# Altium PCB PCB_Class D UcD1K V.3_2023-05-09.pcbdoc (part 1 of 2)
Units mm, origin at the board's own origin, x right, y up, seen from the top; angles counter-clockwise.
Board outline 217.55 x 90.42 mm, 2 copper layers (Top Layer, Bottom Layer); 170 components, 120 nets, 574 pads, 13 vias.
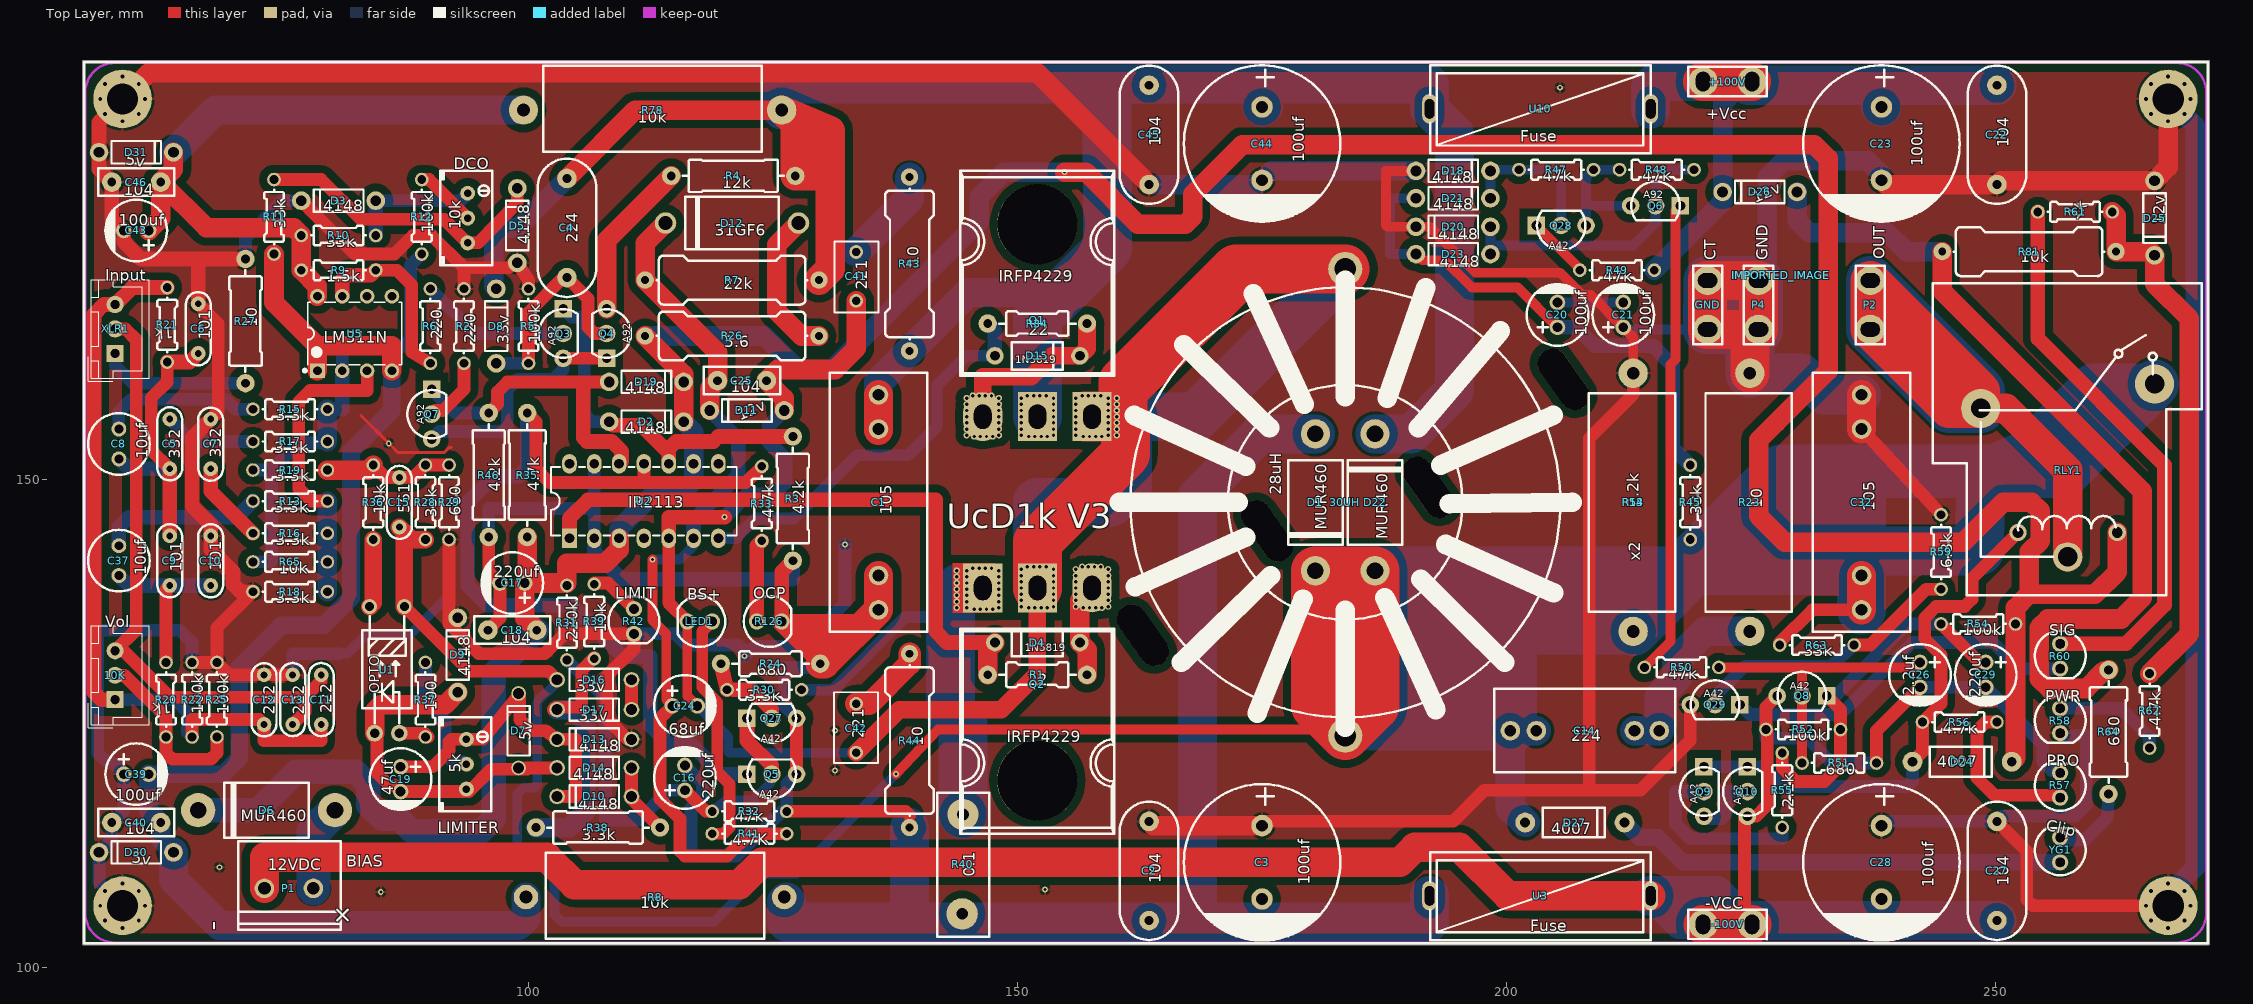
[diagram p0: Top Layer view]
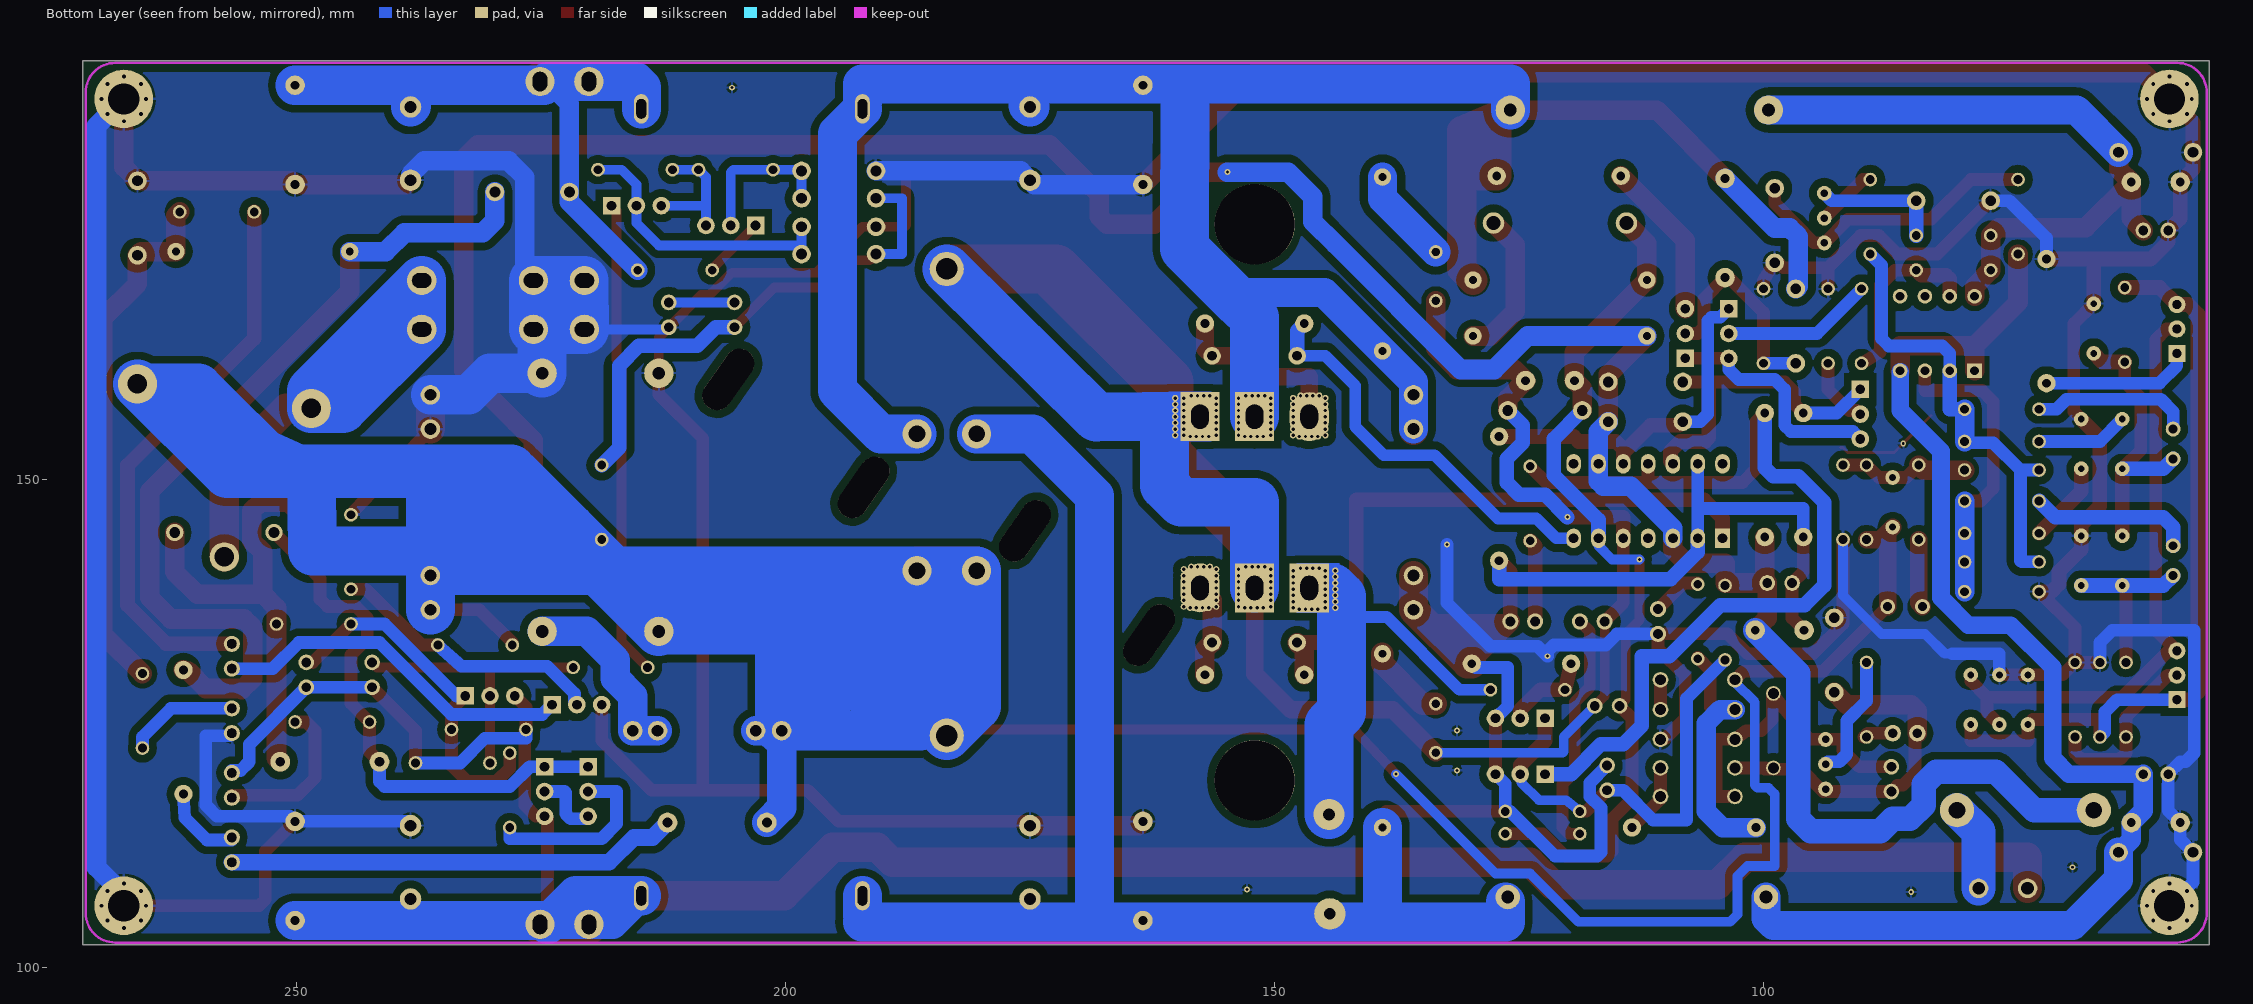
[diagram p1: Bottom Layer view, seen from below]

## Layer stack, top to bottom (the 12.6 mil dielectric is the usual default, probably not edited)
Top Solder: solder mask 0.0102, Solder Resist, Dk 3.5
Top Layer: signal copper 0.0356
Dielectric1: dielectric 0.32, FR-4, Dk 4.8
Bottom Layer: signal copper 0.0356
Bottom Solder: solder mask 0.0102, Solder Resist, Dk 3.5

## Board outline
54.356,192.786 271.907,192.786 271.907,102.362 54.356,102.362

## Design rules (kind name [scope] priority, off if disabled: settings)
Clearance [All] p1: gap=0.8 ignorepadtopadclearanceinfootprint=FALSE
PolygonConnect [All] p1: connectstyle=Relief reliefconductorwidth=0.254 reliefentries=4 polygonreliefangle="90 Angle" airgapwidth=0.254
RoutingVias [All] p1: holewidth=0.711 width=1.27 viastyle="Through Hole" minholewidth=0.711 minwidth=1.27 maxholewidth=0.711 maxwidth=1.27
SolderMaskExpansion [All] p1: expansion=0.102
Width [All] p1: maxlimit=0.254 minlimit=0.254 preferedwidth=0.254
30 further rules are at their usual default settings.

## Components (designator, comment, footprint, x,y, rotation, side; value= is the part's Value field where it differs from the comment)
10K "Vol" "JST 3P" 57.658,127.425 r90 top
30UH "28uH" "TOROID CORE" 183.515,147.618 r0 top
+100V "+Vcc" "FASTON TAB" 222.631,190.671 r180 top
-100V "-VCC" "FASTON TAB" 222.631,104.438 r180 top
C1 "105" "CAP MYLAR 22MM" 135.763,147.618 r0 top
C2 "104" "MYLAR CAP 10MM" 163.449,109.899 r0 top
C3 "100uf" CAP-TH_BD16.0-P7.50-D1.2-FD 175.006,110.788 r270 top
C4 "224" "MYLAR CAP 10MM" 103.886,175.685 r0 top
C5 "332" CERCAP 63.246,153.587 r180 top
C6 "101" CERCAP 66.167,165.398 r0 top
C7 "332" CERCAP 67.437,153.587 r0 top
C8 "10uf" "NONPOLAR CAP 22UF" 58.039,153.587 r270 top
C9 "101" CERCAP 63.246,141.649 r0 top
C10 "101" CERCAP 67.437,141.649 r0 top
C11 "222" CERCAP 78.74,127.425 r180 top
C12 "222" CERCAP 72.898,127.425 r0 top
C13 "222" CERCAP 75.819,127.425 r180 top
C14 "224" CAP-CBB-18.5*8.5 208.026,124.25 r180 top
C15 "561" CERCAP 86.741,147.618 r0 top
C16 "220uf" CAP-TH_BD6.3-P2.50-D1.0-FD 115.951,119.424 r90 top
C17 "220uf" CAP-TH_BD6.3-P2.50-D1.0-FD 98.298,139.363 r180 top
C18 "104" POLYCAP104 98.298,134.537 r90 top
C19 "47uf" CAP-TH_BD6.3-P2.50-D1.0-FD 86.868,119.297 r270 top
C20 "100uf" CAP-TH_BD6.3-P2.50-D1.0-FD 205.232,166.795 r90 top
C21 "100uf" CAP-TH_BD6.3-P2.50-D1.0-FD 211.963,166.795 r90 top
C22 "104" "MYLAR CAP 10MM" 250.19,185.21 r0 top
C23 "100uf" CAP-TH_BD16.0-P7.50-D1.2-FD 238.379,184.321 r270 top
C24 "68uf" CAP-TH_BD6.3-P2.50-D1.0-FD 115.951,126.79 r0 top
C25 "104" POLYCAP104 121.793,160.064 r270 top
C26 "2.2uf" CAP-TH_BD6.3-P2.50-D1.0-FD 242.316,129.965 r270 top
C27 "104" "MYLAR CAP 10MM" 250.19,109.899 r0 top
C28 "100uf" CAP-TH_BD16.0-P7.50-D1.2-FD 238.379,110.788 r270 top
C29 "220uf" CAP-TH_BD6.3-P2.50-D1.0-FD 249.047,129.965 r270 top
C32 "105" "CAP MYLAR 22MM" 236.347,147.618 r180 top
C37 "10uf" "NONPOLAR CAP 22UF" 58.039,141.649 r270 top
C39 "100uf" CAP-TH_BD6.3-P2.50-D1.0-FD 59.817,119.805 r0 top
C40 "104" POLYCAP104 59.817,114.852 r90 top
C41 "221" "WIMA RED" 133.477,170.732 r270 top
C42 "221" "WIMA RED" 133.477,124.504 r90 top
C43 "100uf" CAP-TH_BD6.3-P2.50-D1.0-FD 59.817,175.431 r180 top
C44 "100uf" CAP-TH_BD16.0-P7.50-D1.2-FD 175.006,184.321 r270 top
C45 "104" "MYLAR CAP 10MM" 163.449,185.21 r0 top
C46 "104" POLYCAP104 59.817,180.384 r90 top
D1 "MUR460" MUR460R#1 180.467,147.618 r270 top
D2 "4148" DO-35R#1 112.014,155.873 r180 top
D3 "4148" DO-35R#1 80.518,178.479 r0 top
D4 "1N5819" DO-41_BD2.4-L4.7-P8.70-D0.9-FD 152.019,133.267 r180 top
D5 "4148" DO-35R#1 98.806,175.939 r270 top
D6 "MUR460" MUR460R#2 73.152,116.122 r180 top
D7 "5v" DO-35R#2 98.933,124.25 r270 top
D8 "33v" DO-35R#1 96.647,165.652 r270 top
D9 "4148" DO-35R#1 92.71,131.997 r270 top
D10 "4148" DO-35R#3 106.68,117.519 r0 top
D11 "12v" DO-35R#1 122.301,157.016 r0 top
D12 "31GF6" DO-201_BD5.3-L9.5-P13.50-D1.4-FD 120.777,176.193 r180 top
D13 "4148" DO-35R#3 106.68,123.361 r0 top
D14 "4148" DO-35R#3 106.68,120.44 r180 top
D15 "1N5819" DO-41_BD2.4-L4.7-P8.70-D0.9-FD 152.019,162.604 r0 top
D16 "33v" DO-35R#3 106.68,129.457 r180 top
D17 "33v" DO-35R#3 106.68,126.409 r180 top
D18 "4148" DO-35R#1 194.564,181.527 r180 top
D19 "4148" DO-35R#1 112.014,159.937 r180 top
D20 "4148" DO-35R#1 194.564,175.812 r0 top
D21 "4148" DO-35R#1 194.564,178.733 r180 top
D22 "MUR460" MUR460R#1 186.563,147.618 r90 top
D23 "4148" DO-35R#1 194.564,173.018 r0 top
D24 "4007" 1N4007R 246.634,121.075 r90 top
D25 "12v" DO-35R#1 266.319,176.701 r90 top
D26 "12v" DO-35R#1 225.933,179.368 r0 top
D27 "4007" 1N4007R 207.01,114.852 r90 top
D30 "5v" DO-35R#1 59.817,111.804 r0 top
D31 "5v" DO-35R#1 59.817,183.432 r180 top
DCO "10k" RES-ADJ-TH_3296W 93.726,176.701 r0 top
GND "CT" "FASTON TAB" 220.599,167.811 r270 top
IMPORTED_IMAGE "Comment" IMPORTED_IMAGE 228.052,170.872 r0 top
IMPORTED_IMAGE "Comment" IMPORTED_IMAGE 228.053,170.872 r0 top
LED1 "BS+" "LED B 5MM" 117.475,135.426 r90 top
LIMITER "5k" RES-ADJ-TH_3296W 93.599,120.821 r0 top
P1 "12VDC" CONN-TH_2P-P5.00_WJ300V-5.00-2P 75.438,108.121 r180 top
P2 "OUT" "FASTON TAB" 237.236,167.811 r90 top
P4 "GND" "FASTON TAB" 225.806,167.811 r270 top
Q1 "IRFP4229" TO-247L 152.019,169.208 r0 top
Q2 "IRFP4229" TO-247L 152.019,126.028 r180 top
Q3 "A92" TO-92-3_L4.8-W3.7-P2.54-R 103.505,164.89 r90 top
Q4 "A92" TO-92-3_L4.8-W3.7-P2.54-R 107.95,164.89 r270 top
Q5 "A42" TO-92-3_L4.8-W3.7-P2.54-R 124.841,119.805 r180 top
Q6 "A92" TO-92-3_L4.8-W3.7-P2.54-R 215.265,177.971 r0 top
Q7 "A92" TO-92-3_L4.8-W3.7-P2.54-R 90.043,156.635 r90 top
Q8 "A42" TO-92-3_L4.8-W3.7-P2.54-R 230.251,127.806 r0 top
Q9 "A42" TO-92-3_L4.8-W3.7-P2.54-R 220.218,118.027 r90 top
Q10 "A42" TO-92-3_L4.8-W3.7-P2.54-R 224.663,118.027 r90 top
Q27 "A42" TO-92-3_L4.8-W3.7-P2.54-R 124.841,125.52 r180 top
Q28 "A42" TO-92-3_L4.8-W3.7-P2.54-R 205.613,175.939 r180 top
Q29 "A42" TO-92-3_L4.8-W3.7-P2.54-R 221.361,126.917 r0 top
R1 "22" AXIAL-0.4R 152.019,129.965 r0 top
R2 "220" AXIAL-0.3R 93.345,165.652 r90 top
R3 "4.2k" "AXIAL-0.5 R" 127,147.872 r270 top
R4 "12k" "AXIAL-0.5 R" 120.777,181.019 r180 top
R5 "100k" AXIAL-0.3R 99.949,165.652 r90 top
R6 "220" AXIAL-0.3R 89.916,165.652 r90 top
R7 "22k" AXIAL-0.7 120.777,170.351 r0 top
R8 "10k" "5WATTS RESISTOR"#1 112.903,107.232 r180 top
R9 "1.5k" AXIAL-0.3R 80.518,171.367 r0 top
R10 "33k" AXIAL-0.3R 80.518,174.923 r0 top
R11 "33k" AXIAL-0.3R 73.914,176.828 r90 top
R12 "100k" AXIAL-0.3R 89.027,176.828 r90 top
R13 "3.3k" AXIAL-0.3R 75.565,147.745 r0 top
R14 "2.2k" "5WATTS RESISTOR"#2 212.979,147.618 r270 top
R15 "3.3k" AXIAL-0.3R 75.565,157.143 r0 top
R16 "3.3k" AXIAL-0.3R 75.565,144.443 r0 top
R17 "3.3k" AXIAL-0.3R 75.565,153.841 r0 top
R18 "3.3k" AXIAL-0.3R 75.565,138.474 r0 top
R19 "3.3k" AXIAL-0.3R 75.565,150.92 r180 top
R20 "1k" AXIAL-0.3R 62.865,127.425 r90 top
R21 "1k" AXIAL-0.3R 62.992,165.779 r270 top
R22 "100k" AXIAL-0.3R 65.532,127.425 r270 top
R23 "10" "5WATTS RESISTOR"#2 224.917,147.618 r270 top
R24 "680" AXIAL-0.4R 124.714,131.108 r180 top
R25 "100k" AXIAL-0.3R 68.072,127.425 r90 top
R26 "5.6" AXIAL-0.7 120.777,164.636 r180 top
R27 "10" "AXIAL-0.5 R" 70.993,166.287 r90 top
R28 "33k" AXIAL-0.3R 89.408,147.618 r270 top
R29 "680" AXIAL-0.3R 91.821,147.618 r90 top
R30 "3.3k" AXIAL-0.3R 124.079,128.441 r180 top
R31 "220k" AXIAL-0.3R 103.886,135.299 r90 top
R32 "47k" AXIAL-0.3R 122.555,115.995 r180 top
R33 "4.7k" AXIAL-0.3R 123.825,147.491 r90 top
R34 "22" AXIAL-0.4R 152.019,165.906 r0 top
R35 "4.7k" "AXIAL-0.5 R" 99.822,150.285 r270 top
R36 "10k" AXIAL-0.3R 84.074,147.618 r90 top
R37 "100" AXIAL-0.3R 89.408,127.425 r270 top
R38 "3.3k" "AXIAL-0.5 R" 106.934,114.344 r180 top
R39 "10k" AXIAL-0.3R 106.68,135.426 r270 top
R40 "0.1" "BPR56  5W" 144.399,110.723 r0 top
R41 "4.7K" AXIAL-0.3R 122.555,113.709 r0 top
R42 "LIMIT" "LED R 5MM" 110.744,135.426 r180 top
R43 "10" AXIAL-0.7 138.938,172.002 r90 top
R44 "10" AXIAL-0.7 138.938,123.234 r270 top
R45 "33k" AXIAL-0.3R 218.821,147.618 r270 top
R46 "4.2k" "AXIAL-0.5 R" 95.885,150.285 r270 top
R47 "47k" AXIAL-0.3R 205.105,181.654 r0 top
R48 "47k" AXIAL-0.3R 215.392,181.654 r0 top
R49 "47k" AXIAL-0.3R 211.328,171.367 r180 top
R50 "47k" AXIAL-0.3R 217.932,130.727 r0 top
R51 "680" AXIAL-0.3R 234.061,120.948 r0 top
R52 "100k" AXIAL-0.3R 230.378,124.377 r180 top
R53 "x2" "5WATTS RESISTOR"#2 212.979,147.618 r270 top
R54 "100k" AXIAL-0.3R 248.285,135.172 r180 top
R55 "2.2k" AXIAL-0.3R 228.219,118.154 r270 top
R56 "4.7k" AXIAL-0.3R 246.38,125.139 r0 top
R57 "PRO" "LED R 5MM" 256.667,118.662 r0 top
R58 "PWR" "LED B 5MM" 256.667,125.266 r180 top
R59 "6.8k" AXIAL-0.3R 244.475,142.538 r270 top
R60 "SIG" "LED G 5MM" 256.667,131.87 r180 top
R61 "1k" AXIAL-0.3R 258.191,177.336 r180 top
R62 "4.7k" AXIAL-0.3R 265.811,126.282 r270 top
R63 "33k" AXIAL-0.3R 231.775,133.013 r180 top
R64 "680" "AXIAL-0.5 R" 261.62,123.996 r270 top
R65 "10k" AXIAL-0.3R 75.565,141.522 r0 top
R78 "10k" "5WATTS RESISTOR"#2 112.649,187.75 r180 top
R81 "10k" AXIAL-0.7 253.492,173.272 r0 top
R126 "OCP" "LED R 5MM" 124.587,135.426 r270 top
RLY1 "Relay" "SLA RELAY 12V" 257.429,153.968 r90 top
U1 "OPTO" OPTO 85.471,130.6 r270 top
U2 "IR2113" DIP-14_L19.0-W7.0-P2.54-LS7.6-BL 111.76,147.745 r0 top
U3 "Fuse" FUSE-TH_L22.6-W9.0 203.454,107.359 r180 top
U5 "LM311N" DIP-8R 82.169,164.89 r90 top
U10 "Fuse" FUSE-TH_L22.6-W9.0 203.454,187.877 r180 top
XLR1 "Input" "JST 3P" 57.658,162.858 r90 top
YG1 "Clip" "LED YG 5M" 256.667,112.058 r0 top

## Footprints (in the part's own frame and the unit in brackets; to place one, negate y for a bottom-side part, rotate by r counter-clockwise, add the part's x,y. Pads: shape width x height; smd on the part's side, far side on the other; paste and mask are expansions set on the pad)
1N4007R [mil]
  round 80 hole 40: 1(0,200) 2(0,-200)
  silkscreen extent -60,-120 60,130
"5WATTS RESISTOR"#1 [mm]
  round 2.5 hole 1.3: 1(-13.208,0) 2(13.208,0)
  silkscreen extent -11.18,-4.54 11.18,4.29
"5WATTS RESISTOR"#2 [mm]
  round 3 hole 1.3: 1(-13.208,0) 2(13.208,0)
  silkscreen extent -11.18,-4.54 11.18,4.29
AXIAL-0.3R [mm]
  round 1.4 hole 0.899: 1(-3.81,0) 2(3.81,0)
  silkscreen extent -2.79,-1.02 2.79,1.02
AXIAL-0.4R [mil]
  round 74 hole 35.4: 1(-200,0) 2(200,0)
  silkscreen extent -154,-50 154,50
"AXIAL-0.5 R" [mil]
  round 74 hole 35.4: 1(-255,0) 2(245,0)
  silkscreen extent -209,-65 199,65
AXIAL-0.7 [mil]
  round 70 hole 31.5: 1(350,0) 2(-350,0)
  silkscreen extent -303,-98 303,98
"BPR56  5W" [mm]
  round 3.2 hole 1.2: 1(0,4.961) 2(-0.074,-5.207)
  silkscreen extent -2.63,-7.55 2.7,7.19
"CAP MYLAR 22MM" [mm]
  round 2 hole 1.2: 1(0,-11) 2(0,11)
  silkscreen extent -5,-13.25 5,13.25
CAP-CBB-18.5*8.5 [mm]
  round 2 hole 1.2: 1(-7.62,0) 2(7.62,0)
  silkscreen extent -9.25,-4.27 9.25,4.23
CAP-TH_BD6.3-P2.50-D1.0-FD [mm]
  round 1.6 hole 1: 1(-1.27,0) 2(1.27,0)
  silkscreen extent -3.15,-3.15 3.17,3.15
CAP-TH_BD16.0-P7.50-D1.2-FD [mm]
  round 2.2 hole 1.2: 1(-3.75,0) 2(3.75,0)
  silkscreen extent -8,-8 8,8
CERCAP [mm]
  round 1.5 hole 0.7: 1(0,2.54) 2(0,-2.54)
  silkscreen extent -1.28,-3.75 1.27,3.73
CONN-TH_2P-P5.00_WJ300V-5.00-2P [mm]
  round 2 hole 1.3: 1(-2.504,0) 2(2.504,0)
  silkscreen extent -5.32,-4.8 5.21,4.23
DIP-8R [mm]
  rect 1.5x1.5 hole 0.9: 1(-3.81,3.81)
  round 1.5 hole 0.9: 2(-3.81,1.27) 3(-3.81,-1.27) 4(-3.81,-3.81) 5(3.81,-3.81) 6(3.81,-1.27) 7(3.81,1.27) 8(3.81,3.81)
  silkscreen extent -3.95,-4.8 3.18,5.25
DIP-14_L19.0-W7.0-P2.54-LS7.6-BL [mm]
  rect 1.5x2 hole 1: 1(-7.62,-3.81)
  oval 1.5x2 hole 1: 2(-5.08,-3.81) 3(-2.54,-3.81) 4(0,-3.81) 5(2.54,-3.81) 6(5.08,-3.81) 7(7.62,-3.81) 8(7.62,3.81) 9(5.08,3.81) 10(2.54,3.81) 11(0,3.81) 12(-2.54,3.81) 13(-5.08,3.81) 14(-7.62,3.81)
  silkscreen extent -9.5,-3.5 9.5,3.5
DO-35R#1 [mil]
  round 75 hole 43.31: 1(150,0) 2(-150,0)
  silkscreen extent -100,-45 100,45
DO-35R#2 [mil]
  round 59.05 hole 43.31: 1(150,0) 2(-150,0)
  silkscreen extent -100,-45 100,45
DO-35R#3 [mil]
  round 62.99 hole 43.31: 1(150,0) 2(-150,0)
  silkscreen extent -100,-45 100,45
DO-41_BD2.4-L4.7-P8.70-D0.9-FD [mm]
  round 1.8 hole 1: 1(-4.35,0) 2(4.35,0)
  silkscreen extent -2.6,-1.4 2.6,1.4
DO-201_BD5.3-L9.5-P13.50-D1.4-FD [mm]
  round 2.2 hole 1.4: 1(-6.8,0) 2(6.8,0)
  silkscreen extent -4.8,-2.7 4.8,2.7
"FASTON TAB" [mm]
  round 3 hole 1.5 slot 2 at 90 deg: 1(-2.502,0.003) 1(2.5,0)
  silkscreen extent -4,-1.5 4,1.5
FUSE-TH_L22.6-W9.0 [mm]
  oval 1.5x3 hole 1 slot 2 at 90 deg: 1(-11.313,0) 2(11.313,0)
  silkscreen extent -11.34,-4.45 11.26,4.55
IMPORTED_IMAGE [mm]
"JST 3P" [mm]
  rect 1.75x1.75 hole 0.9: 1(0,0)
  round 1.75 hole 0.9: 2(2.5,0) 3(5,0)
  silkscreen extent -2.85,-3.5 7.55,2.75
"LED B 5MM" [mil]
  round 65 hole 38 slot 38.2 at 90 deg: 1(0,-50) 2(0,50)
  silkscreen extent -102,-102 102,88
"LED G 5MM" [mil]
  round 65 hole 38 slot 38.2 at 90 deg: 1(0,-50) 2(0,50)
  silkscreen extent -102,-102 102,88
"LED R 5MM" [mil]
  round 65 hole 38 slot 38.2 at 90 deg: 1(0,-50) 2(0,50)
  silkscreen extent -102,-102 102,88
"LED YG 5M" [mil]
  round 65 hole 38 slot 38.2 at 90 deg: 1(0,-50) 2(0,50)
  silkscreen extent -102,-102 102,88
MUR460R#1 [mm]
  round 3 hole 1.7: 1(7,0) 2(-7,0)
  silkscreen extent -4.32,-2.8 4.32,2.81
MUR460R#2 [mm]
  round 3.5 hole 1.7: 1(7,0) 2(-7,0)
  silkscreen extent -4.32,-2.8 4.32,2.81
"MYLAR CAP 10MM" [mm]
  round 2 hole 0.914: 1(0,-5.08) 2(0,5.08)
  silkscreen extent -3,-7.06 3,7.09
"NONPOLAR CAP 22UF" [mil]
  round 60 hole 36: 1(-60,0) 2(60,0)
  silkscreen extent -124,-124 124,124
OPTO [mil]
  round 60 hole 36: 1(-250,70) 2(-250,-70)
  round 66.93 hole 38.58: 3(260,50) 4(260,-50)
  silkscreen extent -211,-100 221,100
POLYCAP104 [mm]
  round 2 hole 0.9: 1(0,2.5) 2(0,-2.5)
  silkscreen extent -1.4,-3.9 1.4,3.9
RES-ADJ-TH_3296W [mil]
  round 60 hole 30: 1(0,100.01) 2(0,0.01) 3(0,-99.99)
  silkscreen extent -110,-190 100,190
"SLA RELAY 12V" [mm]
  round 4 hole 2: 2(5.761,-8.9) 5(3.262,8.9)
  round 1.778 hole 1.102: 3(-9.438,-5.08) 4(-9.438,5.08)
  round 3 hole 2: 5(-11.938,0)
  silkscreen extent -15.84,-13.7 16.06,13.8
TO-92-3_L4.8-W3.7-P2.54-R [mm]
  rect 1.8x1.8 hole 1: 1(2.54,0)
  round 1.8 hole 1: 2(0,0) 3(-2.54,0)
  silkscreen extent -2.48,-1.5 2.48,2.48
TO-247L [mm]
  oval 4x5 hole 1.8 slot 2.5 at 90 deg: 1(-5.588,-12.827)
  rect 4x5 hole 1.8 slot 2.5 at 90 deg: 2(0,-12.827) 3(5.588,-12.827)
  round 8.2 hole 8.2 unplated: ""(0,6.858)
  silkscreen extent -7.87,-8.64 7.87,12.32
"TOROID CORE" [mm]
  round 3.5 hole 2.2: 1(0,23.876) 2(0,-23.876)
  silkscreen extent -23.11,-22.99 23.24,22.73
"WIMA RED" [mm]
  round 1.4 hole 0.8 slot 0.805 at 0 deg: 1(2.5,0) 2(-2.5,0)
  silkscreen extent -3.57,-2.21 3.68,2.29

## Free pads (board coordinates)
  round 2 hole 1.2: 1(135.763,140.125) 1(213.106,124.25) 1(236.347,155.111) 2(135.763,155.111) 2(203.073,124.25) 2(236.347,140.125)
  round 0.65 hole 0.4: 2(56.134,106.343) 2(56.134,188.893) 2(56.642,104.819) 2(56.642,107.867) 2(56.642,187.369) 2(56.642,190.417) 2(58.42,104.057) 2(58.42,108.629) 2(58.42,186.607) 2(58.42,191.179) 2(60.071,104.819) 2(60.071,107.867) 2(60.071,187.369) 2(60.071,190.417) 2(60.706,106.343) 2(60.706,188.893) 2(265.43,106.343) 2(265.43,188.893) 2(265.938,104.819) 2(265.938,107.867) 2(265.938,187.369) 2(265.938,190.417) 2(267.716,104.057) 2(267.716,108.629) 2(267.716,186.607) 2(267.716,191.179) 2(269.367,104.819) 2(269.367,107.867) 2(269.367,187.369) 2(269.367,190.417) 2(270.002,106.343) 2(270.002,188.893)
  round 6 hole 3.2: 6(58.42,106.343) 6(58.42,188.893) 6(267.716,106.343) 6(267.716,188.893)
  oval 3x7 hole 3 slot 7 at 125 deg rot 35: 7(162.814,134.029) 7(175.514,144.697) 7(192.024,149.142) 7(205.867,160.191)
  round 0.65 hole 0.35: 8(143.764,136.823) 8(143.764,137.458) 8(143.764,138.093) 8(143.764,138.728) 8(143.764,139.363) 8(143.764,139.998) 8(143.764,140.633) 8(144.78,136.823) 8(144.78,137.458) 8(144.78,138.093) 8(144.78,138.728) 8(144.78,139.363) 8(144.78,139.998) 8(144.78,140.633) 8(144.78,154.476) 8(144.78,155.111) 8(144.78,155.746) 8(144.78,156.381) 8(144.78,157.016) 8(144.78,157.651) 8(144.78,158.286) 8(145.415,140.887) 8(145.415,158.54) 8(145.542,136.696) 8(145.542,154.349) 8(146.05,140.887) 8(146.05,158.54) 8(146.177,136.696) 8(146.177,154.349) 8(146.685,140.887) 8(146.685,158.54) 8(146.812,136.696) 8(146.812,154.349) 8(147.32,140.887) 8(147.32,158.54) 8(147.447,136.696) 8(147.447,154.349) 8(148.082,136.823) 8(148.082,137.458) 8(148.082,138.093) 8(148.082,138.728) 8(148.082,139.363) 8(148.082,139.998) 8(148.082,140.633) 8(148.082,154.476) 8(148.082,155.111) 8(148.082,155.746) 8(148.082,156.381) 8(148.082,157.016) 8(148.082,157.651) 8(148.082,158.286) 8(150.368,136.95) 8(150.368,137.585) 8(150.368,138.22) 8(150.368,138.855) 8(150.368,139.49) 8(150.368,140.125) 8(150.368,140.76) 8(150.368,154.476) 8(150.368,155.111) 8(150.368,155.746) 8(150.368,156.381) 8(150.368,157.016) 8(150.368,157.651) 8(150.368,158.286) 8(151.003,141.014) 8(151.003,158.54) 8(151.13,136.823) 8(151.13,154.349) 8(151.638,141.014) 8(151.638,158.54) 8(151.765,136.823) 8(151.765,154.349) 8(152.273,141.014) 8(152.273,158.54) 8(152.4,136.823) 8(152.4,154.349) 8(152.908,141.014) 8(152.908,158.54) 8(153.035,136.823) 8(153.035,154.349) 8(153.67,136.95) 8(153.67,137.585) 8(153.67,138.22) 8(153.67,138.855) 8(153.67,139.49) 8(153.67,140.125) 8(153.67,140.76) 8(153.67,154.476) 8(153.67,155.111) 8(153.67,155.746) 8(153.67,156.381) 8(153.67,157.016) 8(153.67,157.651) 8(153.67,158.286) 8(155.956,136.95) 8(155.956,137.585) 8(155.956,138.22) 8(155.956,138.855) 8(155.956,139.49) 8(155.956,140.125) 8(155.956,140.76) 8(155.956,154.476) 8(155.956,155.111) 8(155.956,155.746) 8(155.956,156.381) 8(155.956,157.016) 8(155.956,157.651) 8(155.956,158.286) 8(156.591,141.014) 8(156.591,158.54) 8(156.718,136.823) 8(156.718,154.349) 8(157.226,141.014) 8(157.226,158.54) 8(157.353,136.823) 8(157.353,154.349) 8(157.861,141.014) 8(157.861,158.54) 8(157.988,136.823) 8(157.988,154.349) 8(158.496,141.014) 8(158.496,158.54) 8(158.623,136.823) 8(158.623,154.349) 8(159.258,136.95) 8(159.258,137.585) 8(159.258,138.22) 8(159.258,138.855) 8(159.258,139.49) 8(159.258,140.125) 8(159.258,140.76) 8(159.258,154.476) 8(159.258,155.111) 8(159.258,155.746) 8(159.258,156.381) 8(159.258,157.016) 8(159.258,157.651) 8(159.258,158.286) 8(160.147,154.476) 8(160.147,155.111) 8(160.147,155.746) 8(160.147,156.381) 8(160.147,157.016) 8(160.147,157.651) 8(160.147,158.286)
  round 0 smd far side: 9(145.542,138.855) 9(158.623,156.381)
  round 0 smd: 9(145.542,138.855) 9(158.75,156.381)

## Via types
v1: diameter 0.61, hole 0.305, Top Layer to Bottom Layer, tented both sides, 13 vias

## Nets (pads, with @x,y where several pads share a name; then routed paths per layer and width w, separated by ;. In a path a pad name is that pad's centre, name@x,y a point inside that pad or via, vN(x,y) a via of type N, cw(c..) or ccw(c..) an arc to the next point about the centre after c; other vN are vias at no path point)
1: pad.7@162.814,134.029
2: pad.7@175.514,144.697
3: pad.7@192.024,149.142
4: pad.7@205.867,160.191
10K_3: 10K.3 C11.2 C13.1 XLR1.2 | length 63
  Top Layer w1.3: 10K.3@57.658,132.425 58.5,132.425 63.246,127.679 77.089,127.679 ; 10K.3@57.658,132.425 59.817,134.586 59.817,164.255 58.715,165.358 XLR1.2@57.658,165.358 ; C13.1@75.819,124.885 77.089,126.155 77.089,127.679 ; C11.2@78.74,129.965 78.74,129.331 77.089,127.679
C5_1: C5.1 C6.2 C8.2 C9.1 R21.2 | length 28.4
  Top Layer w1.3: R21.2@62.992,161.969 62.992,159.937 61.341,158.286 61.341,152.952 C5.1@63.246,151.047
  Top Layer w1.5: R21.2@62.992,161.969 65.278,161.969 C6.2@66.167,162.858 ; C9.1@63.246,144.189 C5.1@63.246,151.047
  Bottom Layer w1.5: C8.2@58.039,152.063 59.055,151.047 C5.1@63.246,151.047
C14_1: C14.1 pad.1@213.106,124.25 R23.2 | length 19.2
  Bottom Layer w3: pad.1@213.106,124.25 C14.1@215.646,124.25 215.646,127.806 217.424,129.584 217.424,131.489 220.345,134.41 R23.2@224.917,134.41
C20_2: C20.2 C21.2 | length 6.7
  Bottom Layer w1: C20.2@205.232,168.065 C21.2@211.963,168.065
C37_2: C9.2 C10.2 C37.2 R20.2 | length 17.9
  Top Layer w1.3: R20.2@62.865,131.235 62.865,138.728 C9.2@63.246,139.109
  Bottom Layer w1.5: C37.2@58.039,140.125 59.055,139.109 C10.2@67.437,139.109
C42_1: C42.1 R44.2 | length 8.2
  Top Layer w2.3: C42.1@133.477,127.004 134.833,127.004 138.938,131.108 R44.2@138.938,132.124
D5_2: D5.2 DCO.3 R11.2 | length 30.8
  Top Layer w1.3: R11.2@73.914,180.638 78.74,180.638 82.804,176.574 91.313,176.574 93.726,174.161 94.785,174.169 98.806,178.253 D5.2@98.806,179.749
D7_1: C19.2 D7.1 D9.1 D14.1 LIMITER.3 U1.4 | length 35.8
  Top Layer w1.3: U1.4@84.455,123.996 84.455,119.932 85.725,118.662 86.233,118.662 C19.2@86.868,118.027 93.345,118.027 LIMITER.3@93.599,118.281 ; LIMITER.3@93.853,118.027 96.139,120.313 99.822,120.313 ; 99.695,120.44 D14.1@102.87,120.44
  Top Layer w2: U1.4@84.201,123.996 84.201,126.282 84.836,126.917 91.443,126.917 D9.1@92.71,128.187
D7_2: C19.1 D7.2 D10.2 D13.2 LIMITER.1 | length 33
  Top Layer w1.3: C19.1@86.868,120.567 90.17,120.567 91.821,122.218 91.821,123.107 92.075,123.361 93.599,123.361 95.25,123.361 99.06,128.06 99.06,125.393 100.203,124.25 101.727,124.25 D13.2@102.87,123.361 104.775,123.361 104.775,117.519 D10.2@102.87,117.519
D10_1: D10.1 D14.2 R38.1 | length 7.3
  Top Layer w1.3: D14.2@110.49,120.44 D10.1@110.49,117.519 110.49,117.265 R38.1@113.411,114.344
D16_2: D16.2 D17.2 | length 3
  Top Layer w1.3: D17.2@110.49,126.409 D16.2@110.49,129.457
D18_2: D18.2 D21.2 Q28.2 R47.1 | length 15.7
  Bottom Layer w1: D21.2@198.374,178.733 D18.2@198.374,181.527 198.501,181.654 R47.1@201.295,181.654 205.359,181.654 205.613,181.4 Q28.2@205.613,175.939
D20_1: D20.1 D23.1 Q6.2 R48.2 | length 30
  Bottom Layer w1: D20.1@198.374,175.812 D23.1@198.374,173.018 198.374,173.907 212.979,173.907 215.265,176.193 Q6.2@215.265,177.971 215.265,180.13 216.789,181.654 R48.2@219.202,181.654
D22_2: 30UH.2 C14.2 C15.2 C32.2 D1.1 D16.1 D22.2 D27.1 pad.2@203.073,124.25 pad.2@236.347,140.125 R14.2 R28.2 R45.2 R53.2 R63.2 RLY1.2 U1.1 | length 649
  Top Layer w1: v1(137.541,119.805) 141.859,124.377 182.88,124.377 30UH.2@183.515,123.742
  Top Layer w1.3: U1.1@87.249,136.95 93.853,130.346 101.981,130.346 D16.1@102.87,129.457 ; R63.2@227.965,133.267 231.315,136.618 C32.2@236.347,136.618
  Top Layer w1.8: U1.1@87.249,136.95 87.249,144.57 C15.2@86.741,145.078 88.011,143.808 R28.2@89.408,143.808
  Top Layer w3: C32.2@236.347,136.618 pad.2@236.347,140.125
  Top Layer w5: D1.1@180.467,140.619 180.467,126.79 30UH.2@183.515,123.742 ; D1.1@180.467,140.619 183.515,137.57 ; D1.1@180.467,140.619 D22.2@186.563,140.618 ; 30UH.2@183.515,123.742 183.515,137.57 ; 30UH.2@183.515,123.742 183.515,137.57 ; 30UH.2@183.515,123.742 186.563,126.79 D22.2@186.563,140.618 ; 183.515,137.57 D22.2@186.563,140.618
  Bottom Layer w1: D16.1@102.87,129.457 102.87,129.203 100.838,127.171 100.838,118.662 100.584,118.408 99.441,118.408 98.806,117.773 98.806,110.407 101.6,110.407 102.616,109.391 102.616,105.454 103.378,104.692 118.872,104.692 123.825,109.645 127.381,109.645 v1(137.541,119.805)
  Bottom Layer w3: D27.1@201.93,114.852 200.406,116.376 C14.2@200.406,124.25 pad.2@203.073,124.25
  Bottom Layer w4: 186.21,126.437 186.21,124.25 C14.2@200.406,124.25
  Bottom Layer w5: 186.21,134.532 192.636,134.532 ; D22.2@186.21,140.618 186.21,126.438 30UH.2@183.515,123.742 ; 189.103,137.966 210.447,137.966 213.099,140.618 ; 190.881,126.282 190.881,132.777 192.636,134.532 ; C14.2@200.406,124.25 200.633,124.477 200.633,134.532 ; 212.797,140.618 212.979,140.436 R14.2@212.979,134.41 ; 222.028,144.983 234.363,144.983 236.347,142.999 ; 225.744,148.699 226.834,147.609 236.347,147.609 ; 228.092,151.047 252.463,151.047 ; 235.986,150.793 236.347,150.432 C32.2@236.347,136.618 ; pad.2@236.347,140.647 219.216,140.647 R14.2@212.979,134.41 ; 236.347,142.632 248.379,142.632 248.412,142.665 248.539,150.92 248.793,150.539 253.441,152.648 ; 248.465,150.793 251.587,150.793 260.096,159.302 265.902,159.302 266.329,159.729 257.139,150.539 227.584,150.539 217.663,140.618 D1.1@180.467,140.618 ; D1.1@180.467,140.618 183.276,140.618 183.515,140.379 30UH.2@183.515,123.742 ; D1.1@180.467,140.618 180.467,126.79 30UH.2@183.515,123.742 ; 192.636,134.532 192.636,130.623 196.215,127.044 196.215,134.53 212.857,134.532 R14.2@212.979,134.41
D27_2: D27.2 YG1.1 | length 46.3
  Bottom Layer w1.7: D27.2@212.09,114.852 213.614,113.328 215.519,113.328 218.059,110.788 YG1.1@256.667,110.788
GND: C2.2 C3.1 C6.1 C7.1 C10.1 C12.1 C13.2 C21.1 C22.1 C23.2 C27.2 C28.1 C32.1 C39.1 C40.1 C43.2 C44.2 C45.1 C46.1 D3.2 D5.1 D9.2 D13.1 D18.1 D20.2 D25.1 D30.2 D31.1 GND.1 P4.1 pad.1@236.347,155.111 pad.2@56.134,106.343 pad.2@56.134,188.893 pad.2@56.642,104.819 pad.2@56.642,107.867 pad.2@56.642,187.369 pad.2@56.642,190.417 pad.2@58.42,104.057 pad.2@58.42,108.629 pad.2@58.42,186.607 pad.2@58.42,191.179 pad.2@60.071,104.819 pad.2@60.071,107.867 pad.2@60.071,187.369 pad.2@60.071,190.417 pad.2@60.706,106.343 pad.2@60.706,188.893 pad.2@265.43,106.343 pad.2@265.43,188.893 pad.2@265.938,104.819 pad.2@265.938,107.867 pad.2@265.938,187.369 pad.2@265.938,190.417 pad.2@267.716,104.057 pad.2@267.716,108.629 pad.2@267.716,186.607 pad.2@267.716,191.179 pad.2@269.367,104.819 pad.2@269.367,107.867 pad.2@269.367,187.369 pad.2@269.367,190.417 pad.2@270.002,106.343 pad.2@270.002,188.893 pad.6 Q29.3 R2.2 R5.2 R14.1 R18.1 R22.1 R23.1 R25.2 R27.2 R29.1 R42.2 R53.1 R58.2 R59.1 | length 868.2
  Top Layer w0.3: 82.804,156.508 v1(85.653,153.659) 85.975,153.338 86.614,152.698 91.313,152.698 91.821,153.206 92.075,153.206
  Top Layer w1: D18.1@190.754,181.527 187.687,181.527 187.686,175.959 187.833,175.812 D20.2@190.754,175.812 192.151,175.812 196.85,171.113 205.486,171.113 207.772,168.827 208.661,168.827 C21.1@211.963,165.525 212.979,164.509 R14.1@212.979,160.826
  Top Layer w1.3: R22.1@65.532,131.235 R25.2@68.072,131.235 ; C6.1@66.167,167.938 68.199,165.906 68.199,156.889 C7.1@67.437,156.127 ; R18.1@71.755,138.474 68.072,134.791 R25.2@68.072,131.235 ; C13.2@75.819,129.965 69.342,129.965 R25.2@68.072,131.235 ; D3.2@76.708,178.479 82.169,173.018 86.233,173.018 88.138,174.923 90.043,174.923 93.345,171.621 ; R29.1@91.821,143.808 91.821,135.172 94.869,132.124 101.6,132.124 103.632,134.156 R42.2@110.744,134.156 110.744,132.632 107.95,129.838 107.95,125.52 D13.1@110.109,123.361 ; R2.2@93.345,169.462 93.345,171.621 ; D5.1@98.298,172.002 97.917,171.621 93.345,171.621 ; D5.1@98.806,172.129 99.949,170.351 R5.2@99.949,169.462 ; C3.1@175.006,114.538 175.447,114.979 194.564,114.979 197.739,118.154 213.741,118.154 218.821,123.234 Q29.3@218.821,126.917 ; 208.468,118.154 208.468,154.156 212.979,158.667 R14.1@212.979,160.826 ; pad.1@236.347,155.111 R59.1@244.475,146.348 ; C27.2@250.19,114.979 253.238,111.931 253.238,106.978 253.873,106.343 pad.6@267.716,106.343
  Top Layer w1.5: pad.6@58.42,188.893 56.007,186.48 D31.1@56.007,183.432 56.007,181.694 C46.1@57.317,180.384 57.317,176.661 C43.2@58.547,175.431 58.547,174.288 60.325,172.51 R27.2@70.993,172.51 66.548,172.51 66.167,172.129 C6.1@66.167,167.938 ; C7.1@67.437,156.127 65.532,154.222 65.532,147.237 67.437,145.332 C10.1@67.437,144.189 67.437,142.792 69.723,140.506 69.723,139.236 70.485,138.474 R18.1@71.755,138.474
  Top Layer w2: pad.6@58.42,188.893 61.087,191.56 152.019,191.56 C45.1@163.449,180.13 ; C2.2@163.449,114.979 163.89,114.538 C3.1@175.006,114.538 ; C23.2@238.379,180.571 238.82,180.13 C22.1@250.19,180.13 250.571,180.511 D25.1@266.319,180.511 267.716,181.908 pad.6@267.716,188.893
  Top Layer w3: pad.1@236.347,155.111 C32.1@236.347,158.618
  Top Layer w4: GND.1@220.599,165.311 P4.1@225.806,165.311 224.917,164.422 R23.1@224.917,160.826 ; GND.1@220.599,165.311 GND.1@220.602,170.313 P4.1@225.809,170.313 P4.1@225.806,165.311
  Bottom Layer w1: 79.248,132.124 81.407,132.124 83.439,134.156 87.884,134.156 91.821,138.093 R29.1@91.821,143.808 ; C21.1@211.963,165.525 212.177,165.311 GND.1@220.599,165.311
  Bottom Layer w1.3: pad.6@58.42,106.343 56.007,108.756 D30.2@56.007,111.804 57.317,113.114 C40.1@57.317,114.852 58.547,116.082 C39.1@58.547,119.805 57.277,121.075 56.769,121.075 55.88,121.964 55.88,134.537 64.262,134.537 65.532,133.267 R22.1@65.532,131.235 ; R27.2@70.993,172.51 70.993,174.669 74.803,178.479 D3.2@76.708,178.479 ; C13.2@75.819,129.965 75.819,132.124 80.645,132.124 ; R42.2@110.744,134.156 114.935,134.156 116.078,133.013 121.412,133.013 122.047,132.378 v1(122.047,131.87) 123.063,132.886 127.889,132.886 132.334,137.331 v1(132.334,143.3) ; C28.1@238.379,114.538 238.82,114.979 C27.2@250.19,114.979 250.698,115.487 258.191,115.487 259.334,116.63 259.334,123.742 256.921,123.742 R58.2@256.667,123.996
  Bottom Layer w2: C45.1@163.449,180.13 174.565,180.13 C44.2@175.006,180.571 175.962,181.527 D18.1@190.754,181.527 ; P4.1@225.809,170.313 226.695,171.2 226.695,180.892 228.346,182.543 236.982,182.543 238.379,181.146 C23.2@238.379,180.571 ; pad.6@267.716,106.343 267.716,107.486 270.51,110.28 270.51,186.099 pad.6@267.716,188.893
  Bottom Layer w4: R23.1@224.917,160.826 230.251,160.826 232.458,158.619 C32.1@236.347,158.618
  Bottom Layer w5: GND.1@220.599,165.311 P4.1@225.806,165.311 224.917,164.422 R23.1@224.917,160.826 ; GND.1@220.599,165.311 GND.1@220.602,170.313 P4.1@225.809,170.313 P4.1@225.806,165.311
  other v1: 84.836,107.74 152.781,107.994 68.326,110.28 131.318,120.186 131.318,124.25 205.486,190.036
P1_1: D6.2 P1.1 | length 8.9
  Bottom Layer w3.5: P1.1@77.942,108.121 77.942,113.913 D6.2@80.152,116.122
P1_2: -100V.1 C26.2 C27.1 C28.2 C29.2 P1.2 Q8.3 Q10.3 R51.2 R52.2 R57.2 U3.1 | length 269.5
  Top Layer w1.3: -100V.1@224.371,104.436 224.371,115.195 Q10.3@224.663,115.487 225.552,115.487 226.695,116.63 226.695,124.25 R52.2@226.568,124.377 226.568,126.663 Q8.3@227.711,127.806 ; R51.2@237.871,120.948 237.871,124.25 C26.2@242.316,128.695
  Top Layer w3: P1.2@72.934,108.121 72.934,111.296 97.409,111.296 101.854,111.296 104.648,108.502 121.539,108.502 123.825,110.788 189.103,110.788 190.627,112.312 195.199,112.312 200.152,107.359 U3.1@214.767,107.359
  Top Layer w4: -100V.1@220.132,104.438 -100V.1@225.133,104.436
  Bottom Layer w1.3: R52.2@226.568,124.377 226.568,123.488 230.759,123.488 233.299,120.948 R51.2@237.871,120.948 ; C26.2@242.316,128.695 C29.2@249.047,128.695 254.889,122.853 254.889,121.075 255.778,120.186 R57.2@256.667,120.186
  Bottom Layer w3: U3.1@214.767,107.359 217.688,104.438 -100V.1@219.369,104.438 ; -100V.1@219.37,104.438 -100V.1@224.371,104.436
  Bottom Layer w4: U3.1@214.767,107.359 221.447,107.359 224.371,104.436 224.754,104.819 C27.1@250.19,104.819
Q1_1: D15.2 pad.8@144.78,154.476 pad.8@144.78,155.111 pad.8@144.78,155.746 pad.8@144.78,156.381 pad.8@144.78,157.016 pad.8@144.78,157.651 pad.8@144.78,158.286 pad.8@145.415,158.54 pad.8@145.542,154.349 pad.8@146.05,158.54 pad.8@146.177,154.349 pad.8@146.685,158.54 pad.8@146.812,154.349 pad.8@147.32,158.54 pad.8@147.447,154.349 pad.8@148.082,154.476 pad.8@148.082,155.111 pad.8@148.082,155.746 pad.8@148.082,156.381 pad.8@148.082,157.016 pad.8@148.082,157.651 pad.8@148.082,158.286 Q1.1 R34.2 | length 18.5
  Top Layer w1.8: Q1.1@146.431,156.381 146.431,160.445 151.384,160.445 153.543,162.604 D15.2@156.369,162.604 ; D15.2@156.369,162.604 157.099,163.334 R34.2@157.099,165.906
